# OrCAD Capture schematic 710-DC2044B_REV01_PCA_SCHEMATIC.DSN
size C; title: HIGH VOLTAGE BUCK/BOOST MULTI-CHEMISTRY BATTERY CHARGER; rev: 01
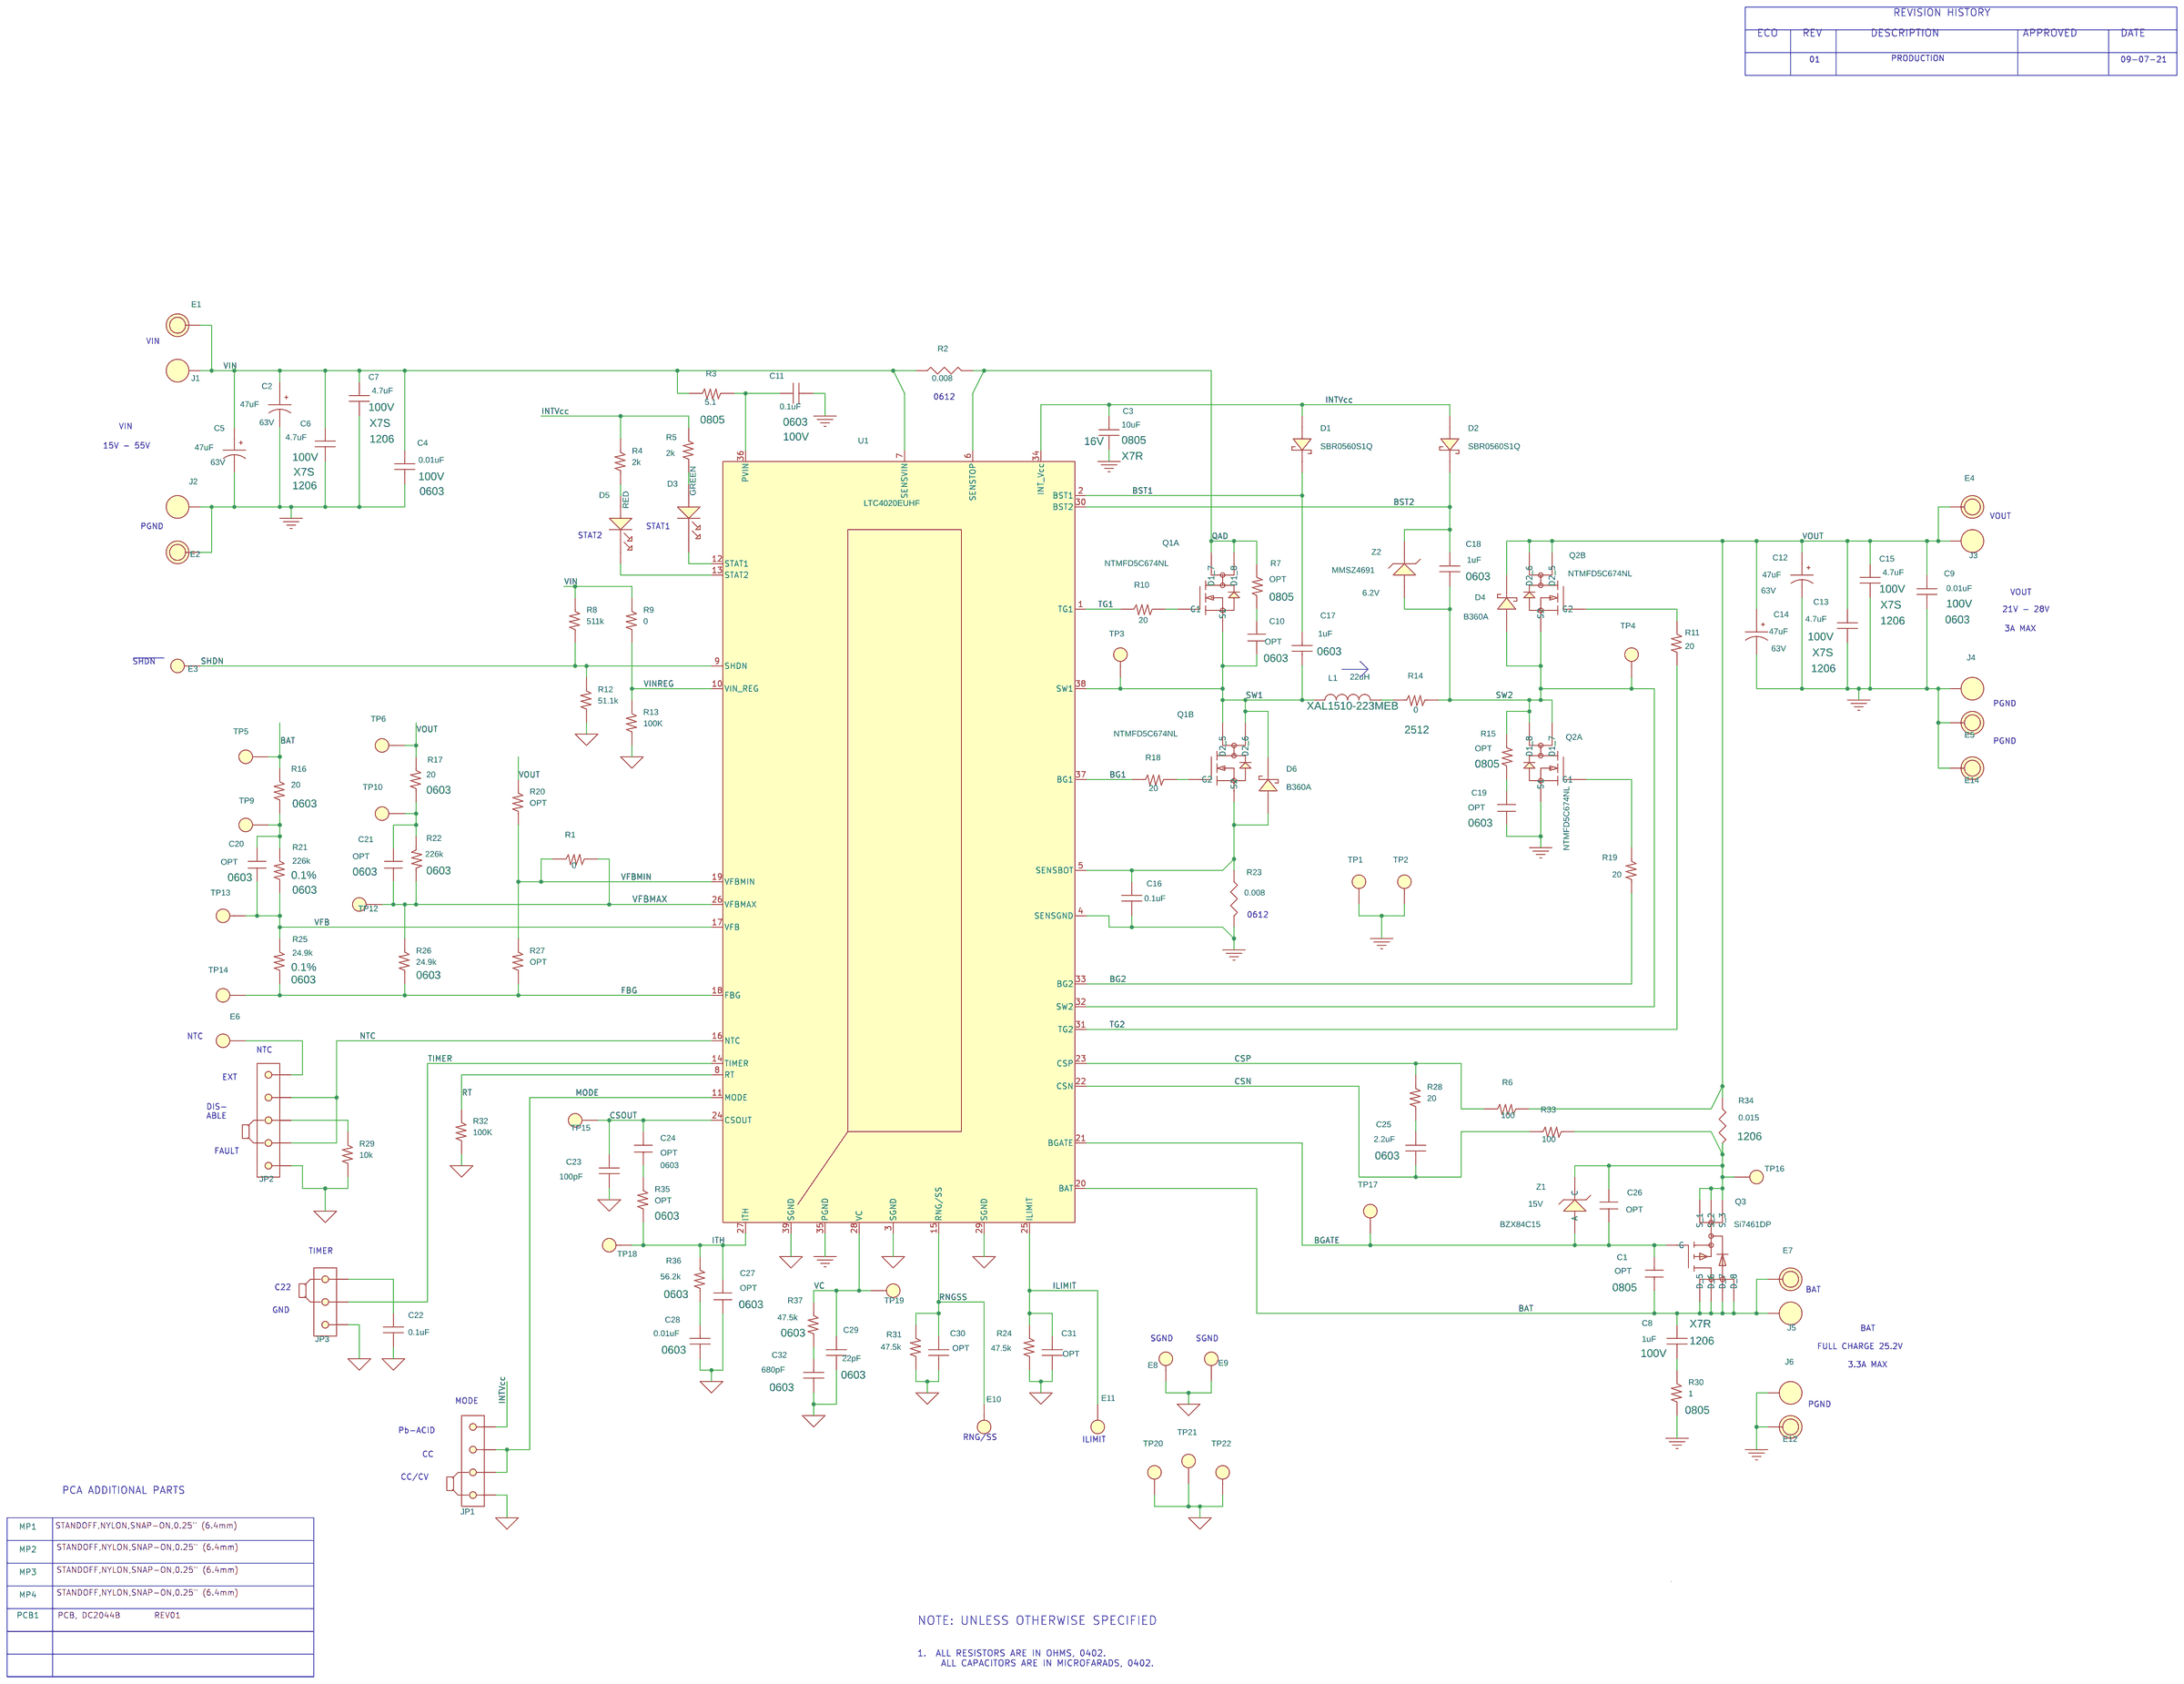
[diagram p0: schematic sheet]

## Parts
C1  OPT  [CC0805N]
C2  47uF  [PANASONIC_ZA_8X10.2]
C3  10uF  [CC0805N]
C4  0.01uF  [CC0603N]
C5  47uF  [PANASONIC_ZA_8X10.2]
C6  4.7uF  [CC1206N]
C7  4.7uF  [CC1206N]
C8  1uF  [CC1206N]
C9  0.01uF  [CC0603N]
C10  OPT  [CC0603N]
C11  0.1uF  [CC0603N]
C12  47uF  [PANASONIC_ZA_8X10.2]
C13  4.7uF  [CC1206N]
C14  47uF  [PANASONIC_ZA_8X10.2]
C15  4.7uF  [CC1206N]
C16  0.1uF  [CC0402N]
C17  1uF  [CC0603N]
C18  1uF  [CC0603N]
C19  OPT  [CC0603N]
C20  OPT  [CC0603N]
C21  OPT  [CC0603N]
C22  0.1uF  [CC0402N]
C23  100pF  [CC0402N]
C24  OPT  [CC0603N]
C25  2.2uF  [CC0603N]
C26  OPT  [CC0603N]
C27  OPT  [CC0603N]
C28  0.01uF  [CC0603N]
C29  22pF  [CC0603N]
C30  OPT  [CC0402N]
C31  OPT  [CC0402N]
C32  680pF  [CC0603N]
D1  SBR0560S1Q  [SOD-123N]
D2  SBR0560S1Q  [SOD-123N]
D3  GREEN  [LED_0603]
D4  B360A  [SMA-N]
D5  RED  [LED_0603]
D6  B360A  [SMA-N]
E1  TEST POINT  [MILLMAX2501]
E2  TEST POINT  [MILLMAX2501]
E3  TEST POINT  [MILLMAX2308]
E4  TEST POINT  [MILLMAX2501]
E5  TEST POINT  [MILLMAX2501]
E6  TEST POINT  [MILLMAX2308]
E7  TEST POINT  [MILLMAX2501]
E8  TEST POINT  [MILLMAX2308]
E9  TEST POINT  [MILLMAX2308]
E10  TEST POINT  [MILLMAX2308]
E11  TEST POINT  [MILLMAX2308]
E12  TEST POINT  [MILLMAX2501]
E14  TEST POINT  [MILLMAX2501]
J1  BANANA JACK  [KEY-575-4]
J2  BANANA JACK  [KEY-575-4]
J3  BANANA JACK  [KEY-575-4]
J4  BANANA JACK  [KEY-575-4]
J5  BANANA JACK  [KEY-575-4]
J6  BANANA JACK  [KEY-575-4]
JP1  HDR  [HD1X4-079]
JP2  HEADER  [HD1X5-079]
JP3  HDR  [HD1X3-079]
L1  22uH  [COILCRAFT-XAL1510]
MP1  STANDOFF  [MTG-8831]
MP2  STANDOFF  [MTG-8831]
MP3  STANDOFF  [MTG-8831]
MP4  STANDOFF  [MTG-8831]
PCB1  PCB, DC2044B
Q1  NTMFD5C674NL  [ONSEMI-DFN8-SO-8FL]  (sections A,B)
Q2  NTMFD5C674NL  [ONSEMI-DFN8-SO-8FL]  (sections A,B)
Q3  Si7461DP  [VISHAY_PPAK_SO-8]
R1  0  [CR0402N]
R2  0.008  [SUSUMU-PRL1632]
R3  5.1  [CR0805N]
R4  2k  [CR0402N]
R5  2k  [CR0402N]
R6  100  [CR0402N]
R7  OPT  [CR0805M]
R8  511k  [CR0402N]
R9  0  [CR0402N]
R10  20  [CR0402N]
R11  20  [CR0402N]
R12  51.1k  [CR0402N]
R13  100K  [CR0402N]
R14  0  [VISHAY-WSL_9-2512]
R15  OPT  [CR0805M]
R16  20  [CR0603N]
R17  20  [CR0603N]
R18  20  [CR0402N]
R19  20  [CR0402N]
R20  OPT  [CR0402N]
R21  226k  [CR0603N]
R22  226k  [CR0603N]
R23  0.008  [SUSUMU-PRL1632]
R24  47.5k  [CR0402N]
R25  24.9k  [CR0603N]
R26  24.9k  [CR0603N]
R27  OPT  [CR0402N]
R28  20  [CR0402N]
R29  10k  [CR0402N]
R30  1  [CR0805M]
R31  47.5k  [CR0402N]
R32  100K  [CR0402N]
R33  100  [CR0402N]
R34  0.015  [SUSUMU-KRL1632]
R35  OPT  [CR0603N]
R36  56.2k  [CR0603N]
R37  47.5k  [CR0603N]
TP1  TEST PAD  [PADSTYLE1]
TP2  TEST PAD  [PADSTYLE1]
TP3  TEST PAD  [PADSTYLE1]
TP4  TEST PAD  [PADSTYLE1]
TP5  TEST PAD  [PADSTYLE1]
TP6  TEST PAD  [PADSTYLE1]
TP9  TEST PAD  [PADSTYLE1]
TP10  TEST PAD  [PADSTYLE1]
TP12  TEST PAD  [PADSTYLE1]
TP13  TEST PAD  [PADSTYLE1]
TP14  TEST PAD  [PADSTYLE1]
TP15  TEST PAD  [PADSTYLE1]
TP16  TEST PAD  [PADSTYLE1]
TP17  TEST PAD  [PADSTYLE1]
TP18  TEST PAD  [PADSTYLE1]
TP19  TEST PAD  [PADSTYLE1]
TP20  TEST PAD  [PADSTYLE1]
TP21  TEST PAD  [PADSTYLE1]
TP22  TEST PAD  [PADSTYLE1]
U1  LTC4020EUHF  [LTC-UHF-38-1701]
XJP1  SHUNT  [SAMTEC-SHUNT-079]
XJP2  SHUNT  [SAMTEC-SHUNT-079]
XJP3  SHUNT  [SAMTEC-SHUNT-079]
Z1  BZX84C15  [SOT23-3N]
Z2  MMSZ4691  [SOD-123N]

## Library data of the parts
C1 = CAP_ALT: CAP., OPTION, 0805; CLASS: DISCRETE; PART_NUMBER: 150-3036; Package Size: 0805; Package Type: SMD
C2 C5 C12 C14 = CAP_P_ALT: CAP.,47uF,ALUM ELECT.,63V,20%,SMD,8.0x10.2 mm,AEC-Q200; CLASS: DISCRETE; Dielectric Type: ALUM ELECT.; Inventory Qty: 0; Manufacturer: PANASONIC; Manufacturer PN: EEHZA1J470P; PART_NUMBER: 150-0969; Package Size: SMD,8.0x10.2 mm; Rated Voltage: 63V; Tolerance: 20%
C3 = CAP: CAP.,10uF,X7R,16V,10%,0805; CLASS: DISCRETE; Dielectric Type: X7R; FPLIST: CC0805N,CC0805L,CC0805M; Inventory Qty: 22441; Manufacturer: TAIYO YUDEN; Manufacturer PN: EMK212BB7106MG-T; PART_NUMBER: 150-3231; Package Size: 0805; Package Type: SMD; Rated Voltage: 16V; Tolerance: 10%
C4 C9 = CAP: CAP.,0.01uF,X7R,100V,10%,0603,AEC-Q200; CLASS: DISCRETE; Dielectric Type: X7R; FPLIST: CC0603N,CC0603L,CC0603M; Inventory Qty: 20068; Manufacturer: MURATA; Manufacturer PN: GCJ188R72A103KA01D; PART_NUMBER: 150-0511; Package Size: 0603; Rated Voltage: 100V; Tolerance: 10%
C6 C7 C13 C15 = CAP: CAP.,4.7uF,X7S,100V,20%,1206; CLASS: DISCRETE; Dielectric Type: X7S; FPLIST: CC1206N,CC1206L,CC1206M; Inventory Qty: 11240; Manufacturer: AVX; Manufacturer PN: 12061Z475MAT2A; PART_NUMBER: 150-2278; Package Size: 1206; Rated Voltage: 100V; Tolerance: 20%
C8 = CAP: CAP.,1uF,X7R,100V,10%,1206,AEC-Q200; CLASS: DISCRETE; Dielectric Type: X7R; FPLIST: CC1206N,CC1206L,CC1206M; Inventory Qty: 800; Manufacturer: TDK; Manufacturer PN: CGA5L2X7R2A105K160AA; PART_NUMBER: 150-1253; Package Size: 1206; Rated Voltage: 100V; Temperature Coefficient: X7R; Tolerance: 10%
C10 C19-C21 C24 C26 C27 = CAP_ALT: CAP., OPTION, 0603; CLASS: DISCRETE; PART_NUMBER: 150-3038; Package Size: 0603; Package Type: SMD
C11 = CAP: CAP.,0.1uF,X7R,100V,10%,0603,AEC-Q200; CLASS: DISCRETE; Dielectric Type: X7R; FPLIST: CC0603N,CC0603L,CC0603M; Inventory Qty: 7960; Manufacturer: TAIYO YUDEN; Manufacturer PN: HMK107B7104KAHT; PART_NUMBER: 150-2623; Package Size: 0603; Rated Voltage: 100V; Tolerance: 10%
C16 C22 = CAP: CAP.,0.1uF,X7R,16V,10%,0402,AEC-Q200; CLASS: DISCRETE; Dielectric Type: X7R; FPLIST: CC0402N,CC0402L,CC0402M; Inventory Qty: 23025; Manufacturer: MURATA; Manufacturer PN: GCM155R71C104KA55D; PART_NUMBER: 150-0506; Package Size: 0402; Rated Voltage: 16V; Tolerance: 10%
C17 C18 = CAP: CAP.,1uF,X7R,16V,10%,0603; CLASS: DISCRETE; Dielectric Type: X7R; FPLIST: CC0603N,CC0603L,CC0603M; Inventory Qty: 29099; Manufacturer: KEMET; Manufacturer PN: C0603C105K4RAC7867; PART_NUMBER: 150-0179; Package Size: 0603; Rated Voltage: 16V; Tolerance: 10%
C23 = CAP: CAP.,100pF,C0G,50V,5%,0402; CLASS: DISCRETE; Dielectric Type: C0G; FPLIST: CC0402N,CC0402L,CC0402M; Inventory Qty: 62393; Manufacturer: AVX; Manufacturer PN: 04025A101JAT2A; PART_NUMBER: 150-0115; Package Size: 0402; Rated Voltage: 50V; Tolerance: 5%
C25 = CAP: CAP.,2.2uF,X7R,10V,10%,0603; CLASS: DISCRETE; Dielectric Type: X7R; FPLIST: CC0603N,CC0603L,CC0603M; Inventory Qty: 13521; Manufacturer: MURATA; Manufacturer PN: GRM188R71A225KE15D; PART_NUMBER: 150-2083; Package Size: 0603; Rated Voltage: 10V; Tolerance: 10%
C28 = CAP: CAP.,0.01uF,X7R,50V,10%,0603; CLASS: DISCRETE; Dielectric Type: X7R; FPLIST: CC0603N,CC0603L,CC0603M; Inventory Qty: 28283; Manufacturer: AVX; Manufacturer PN: 06035C103KAT2A; PART_NUMBER: 150-0002; Package Size: 0603; Rated Voltage: 50V; Tolerance: 10%
C29 = CAP: CAP.,22pF,C0G,25V,10%,0603; CLASS: DISCRETE; Dielectric Type: C0G; FPLIST: CC0603N,CC0603L,CC0603M; Inventory Qty: 12404; Manufacturer: AVX; Manufacturer PN: 06033A220KAT2A; PART_NUMBER: 150-3274; Package Size: 0603; Rated Voltage: 25V; Tolerance: 10%
C30 C31 = CAP: CAP., OPTION, 0402; CLASS: DISCRETE; FPLIST: CC0402N,CC0402L,CC0402M; PART_NUMBER: 150-3148; Package Size: 0402; Package Type: SMD
C32 = CAP: CAP.,680pF,C0G,25V,5%,0603; CLASS: DISCRETE; Dielectric Type: C0G; FPLIST: CC0603N,CC0603L,CC0603M; Inventory Qty: 8685; Manufacturer: AVX; Manufacturer PN: 06033A681JAT2A; PART_NUMBER: 150-0275; Package Size: 0603; Rated Voltage: 25V; Tolerance: 5%
D1 D2 = DIODE_SCHOTTKY_A_ALT: DIODE,SBR,60V,500mA,SOD123; CLASS: DISCRETE; Inventory Qty: 0; Manufacturer: DIODES INC.; Manufacturer PN: SBR0560S1Q-7; PART_NUMBER: 210-0561; Package Size: SOD-123; Package Type: SOD123; Rated Voltage or Zener Voltage: 60V
D3 = LED_ALT: LED,GREEN,WATER-CLEAR,0603; CLASS: DISCRETE; Inventory Qty: 49236; Manufacturer: LITE-ON; Manufacturer PN: LTST-C190KGKT; PART_NUMBER: 270-0051; Package Type: 0603
D4 D6 = DIODE_SCHOTTKY_A_ALT: DIODE,SCHOTTKY RECTIFIER,60V,3A,4.6mm X 2.92mm; CLASS: DISCRETE; FPLIST: SMA-N,SMA-L,SMA-M,SMA; Inventory Qty: 1450; Manufacturer: DIODES INC.; Manufacturer PN: B360A-13-F; Max Forward Current or Rated Power: 3A; PART_NUMBER: 210-0103; Package Type: 4.6mm X 2.92mm; Rated Voltage or Zener Voltage: 60V
D5 = LED_ALT: LED,RED,WATER-CLEAR,0603; CLASS: DISCRETE; Inventory Qty: 15266; Manufacturer: LITE-ON; Manufacturer PN: LTST-C193KRKT-5A; PART_NUMBER: 270-0070; Package Size: 0603 (1608 Metric); Package Type: 0603
E1 E2 E4 E5 E7 E12 E14 = TURRET_A: TEST POINT,TURRET,0.094" MTG. HOLE,PCB 0.062" THK; CLASS: IO; Inventory Qty: 823526; Manufacturer: MILL-MAX; Manufacturer PN: 2501-2-00-80-00-00-07-0; PART_NUMBER: 260-0003
E3 E6 E8-E11 = TEST_POINT_.156_MILL-MAX_2308: TEST POINT,TURRET,0.064" MTG. HOLE,PCB 0.062" THK; CLASS: IO; FPLIST: MILLMAX2308,MILLMAX2308-2; Inventory Qty: 1142083; Manufacturer: MILL-MAX; Manufacturer PN: 2308-2-00-80-00-00-07-0; PART_NUMBER: 260-0004
J1-J6 = BANANA_KEYSTONE-575-4_C: CONN.,BANANA JACK,FEMALE,THT,NON-INSULATED,SWAGE,0.218"; CLASS: IO; Inventory Qty: 203061; Manufacturer: KEYSTONE; Manufacturer PN: 575-4; PART_NUMBER: 250-0428
JP1 = HDR1X4: CONN.,HDR,MALE,1x4,2mm,VERT,ST,THT; CLASS: IO; Inventory Qty: 11710; Manufacturer: SULLINS CONNECTOR SOLUTIONS; Manufacturer PN: NRPN041PAEN-RC; PART_NUMBER: 250-0431
JP2 = HDR1X5: CONN.,HEADER,MALE,1X5,2mm,ST, THT; CLASS: IO; Inventory Qty: 950; Manufacturer: SULLINS CONNECTOR SOLUTIONS; Manufacturer PN: NRPN051PAEN-RC; PART_NUMBER: 250-0564
JP3 = 1X3: CONN.,HDR,MALE,1x3,2mm,VERT,ST,THT,NO SUBS. ALLOWED; CLASS: IO; Inventory Qty: 7904; Manufacturer: SAMTEC; Manufacturer PN: TMM-103-02-L-S; PART_NUMBER: 250-0638
L1 = IND_ALT: IND.,22uH,PWR,20%,14A,16mOHMS,16.2x15.2mm,AEC-Q200; CLASS: DISCRETE; Inventory Qty: 0; Manufacturer: COILCRAFT; Manufacturer PN: XAL1510-223MEB; PART_NUMBER: 200-0363; Package Size: 16.2x15.2mm; Tolerance: 20%
MP1-MP4 = BLANK_MECHANICAL_PART: STANDOFF,NYLON,SNAP-ON,0.25" (6.4mm); CLASS: DISCRETE; Inventory Qty: 227624; Manufacturer: KEYSTONE; Manufacturer PN: 8831; PART_NUMBER: 763-0006
PCB1 = BLANK_PCB_PART: BOM Notes: REV01; CLASS: DISCRETE; Inventory Qty: 0; Manufacturer: ADI APPROVED SUPPLIER; Manufacturer PN: 600-DC2044B; PART_NUMBER: 600-DC2044B
Q1 Q2 = DUAL_8P_N-CH_TYPE1A: XSTR.,MOSFET,DUAL N-CH,60V,42A,DFN-8 (SO8FL); CLASS: DISCRETE; Inventory Qty: 0; Manufacturer: ON Semiconductor; Manufacturer PN: NTMFD5C674NLT1G; PART_NUMBER: 240-0596; Package Size: DFN-8; Package Type: DFN-8 (SO8FL); Polarity: N-Channel; Rated Voltage: 60V
Q3 = 8P_P-CH_TYPE1A: XSTR.,MOSFET, P-CH,60V,8.6A,PowerPAK SO-8; CLASS: DISCRETE; Inventory Qty: 1926; Manufacturer: VISHAY; Manufacturer PN: Si7461DP-T1-GE3; PART_NUMBER: 240-0180; Package Type: PowerPAK SO-8; Rated Voltage: 60V
R1 R9 = RES_ALT: RES.,0 OHM,1/16W,0402; CLASS: DISCRETE; FPLIST: CR0402N,CR0402L,CR0402M; Inventory Qty: 264417; Manufacturer: ROHM; Manufacturer PN: MCR01MZPJ000; PART_NUMBER: 100-0215; Package Size: 0402; Rated Power: 1/16W
R2 R23 = RES: RES.,0.008 OHMS,1%,1W,1206,LONG-SIDE,SENSE; CLASS: DISCRETE; Inventory Qty: 0; Manufacturer: Susumu; Manufacturer PN: PRL1632-R008-F-T1; PART_NUMBER: 100-1805; Package Size: 1206,LONG-SIDE; Rated Power: 1W; Temperature Coefficient: 0/ +350ppm; Tolerance: 1%
R3 = RES_ALT: RES.,5.1 OHMS,5%,1/8W,0805,AEC-Q200; CLASS: DISCRETE; FPLIST: CR0805N,CR0805L,CR0805M; Inventory Qty: 9698; Manufacturer: VISHAY; Manufacturer PN: CRCW08055R10JNEA; PART_NUMBER: 100-2080; Package Size: 0805; Rated Power: 1/8W; Temperature Coefficient: +/-200PPM; Tolerance: 5%
R4 R5 = RES_ALT: RES.,2k OHMS,1%,1/16W,0402,AEC-Q200; CLASS: DISCRETE; FPLIST: CR0402N,CR0402L,CR0402M; Inventory Qty: 54049; Manufacturer: VISHAY; Manufacturer PN: CRCW04022K00FKED; PART_NUMBER: 100-0018; Package Size: 0402; Rated Power: 1/16W; Temperature Coefficient: 100ppm/C; Tolerance: 1%
R6 R33 = RES_ALT: RES.,100 OHMS,1%,1/16W,0402,AEC-Q200; CLASS: DISCRETE; FPLIST: CR0402N,CR0402L,CR0402M; Inventory Qty: 89473; Manufacturer: KOA SPEER; Manufacturer PN: RK73H1ETTP1000F; PART_NUMBER: 100-0175; Package Size: 0402; Rated Power: 1/16W; Temperature Coefficient: 100ppm/C; Tolerance: 1%
R7 R15 = RES_ALT: RES., OPTION, 0805; CLASS: DISCRETE; PART_NUMBER: 100-2558; Package Size: 0805
R8 = RES_ALT: RES.,511k OHMS,1%,1/16W,0402,AEC-Q200; CLASS: DISCRETE; FPLIST: CR0402N,CR0402L,CR0402M; Inventory Qty: 20064; Manufacturer: NIC; Manufacturer PN: NRC04F5113TRF; PART_NUMBER: 100-0583; Package Size: 0402; Rated Power: 1/16W; Temperature Coefficient: +/-100PPM; Tolerance: 1%
R10 R11 R18 R19 = RES_ALT: RES.,20 OHMS,1%,1/16W,0402; CLASS: DISCRETE; FPLIST: CR0402N,CR0402L,CR0402M; Inventory Qty: 8000; Manufacturer: VISHAY; Manufacturer PN: CRCW040220R0FKED; PART_NUMBER: 100-2322; Package Size: 0402; Rated Power: 1/16W; Temperature Coefficient: 100ppm/C; Tolerance: 1%
R12 = RES_ALT: RES.,51.1k OHMS,1%,1/16W,0402,AEC-Q200; CLASS: DISCRETE; FPLIST: CR0402N,CR0402L,CR0402M; Inventory Qty: 20000; Manufacturer: STACKPOLE ELECTRONICS, INC.; Manufacturer PN: RMCF0402FT51K1; PART_NUMBER: 100-2544; Package Size: 0402; Rated Power: 1/16W; Temperature Coefficient: 100ppm/C; Tolerance: 1%
R13 R32 = RES_ALT: RES.,100k OHMS,1%,1/16W,0402,AEC-Q200; CLASS: DISCRETE; FPLIST: CR0402N,CR0402L,CR0402M; Inventory Qty: 92256; Manufacturer: NIC; Manufacturer PN: NRC04F1003TRF; PART_NUMBER: 100-0601; Package Size: 0402; Rated Power: 1/16W; Temperature Coefficient: 100PPM; Tolerance: 1%
R14 = RES_ALT: RES.,0 OHM,200A,2512,COPPER,SENSE; CLASS: DISCRETE; FPLIST: CR2512N,CR2512L,CR2512M,VISHAY-WSL2512; Inventory Qty: 7479; Manufacturer: VISHAY; Manufacturer PN: WSL251200000ZEA9; PART_NUMBER: 100-0588; Package Size: 2512; Rated Power: 200A; Temperature Coefficient: +/-3900ppm
R16 R17 = RES_ALT: RES.,20 OHMS,1%,1/10W,0603; CLASS: DISCRETE; FPLIST: CR0603N,CR0603L,CR0603M; Inventory Qty: 10000; Manufacturer: YAGEO; Manufacturer PN: RC0603FR-0720RL; PART_NUMBER: 100-0703; Package Size: 0603; Rated Power: 1/10W; Temperature Coefficient: 100PPM; Tolerance: 1%
R20 R27 = RES_ALT: RES., OPTION, 0402; CLASS: DISCRETE; PART_NUMBER: 100-0357; Package Size: 0402
R21 = RES_ALT: RES.,226k OHMS,0.1%,1/10W,0603,High Stability; CLASS: DISCRETE; Inventory Qty: 4724; Manufacturer: VISHAY; Manufacturer PN: TNPW0603226KBEEA; PART_NUMBER: 100-2083; Package Size: 0603; Rated Power: 1/10W; Temperature Coefficient: +/-25PPM; Tolerance: 0.1%
R22 = RES_ALT: RES.,226k OHMS,1%,1/10W,0603; CLASS: DISCRETE; FPLIST: CR0603N,CR0603L,CR0603M; Inventory Qty: 26500; Manufacturer: NIC; Manufacturer PN: NRC06F2263TRF; PART_NUMBER: 100-2671; Package Size: 0603; Rated Power: 1/10W; Temperature Coefficient: 100ppm/C; Tolerance: 1%
R24 R31 = RES_ALT: RES.,47.5k OHMS,1%,1/16W,0402; CLASS: DISCRETE; FPLIST: CR0402N,CR0402L,CR0402M; Inventory Qty: 10000; Manufacturer: NIC; Manufacturer PN: NRC04F4752TRF; PART_NUMBER: 100-0390; Package Size: 0402; Rated Power: 1/16W; Temperature Coefficient: 100ppm/C; Tolerance: 1%
R25 = RES_ALT: RES.,24.9k OHMS,0.1%,1/8W,0603,AEC-Q00; CLASS: DISCRETE; Inventory Qty: 0; Manufacturer: VISHAY; Manufacturer PN: TNPW060324K9BEEA; PART_NUMBER: 100-1806; Package Size: 0603; Rated Power: 1/8W; Temperature Coefficient: +/-25ppm; Tolerance: 0.1%
R26 = RES_ALT: RES.,24.9k OHMS,1%,1/10W,0603,AEC-Q200; CLASS: DISCRETE; FPLIST: CR0603N,CR0603L,CR0603M; Inventory Qty: 22314; Manufacturer: NIC; Manufacturer PN: NRC06F2492TRF; PART_NUMBER: 100-0037; Package Size: 0603; Rated Power: 1/10W; Temperature Coefficient: 100ppm/C; Tolerance: 1%
R28 = RES_ALT: RES.,20 OHMS,1%,1/16W,0402,AEC-Q200; CLASS: DISCRETE; FPLIST: CR0402N,CR0402L,CR0402M; Inventory Qty: 29845; Manufacturer: NIC; Manufacturer PN: NRC04F20R0TRF; PART_NUMBER: 100-0250; Package Size: 0402; Rated Power: 1/16W; Temperature Coefficient: 100ppm; Tolerance: 1%
R29 = RES_ALT: RES.,10k OHMS,1%,1/10W,0402,AEC-Q200; CLASS: DISCRETE; FPLIST: CR0402N,CR0402L,CR0402M; Inventory Qty: 88953; Manufacturer: KOA SPEER; Manufacturer PN: RK73H1ETTP1002F; PART_NUMBER: 100-0724; Package Size: 0402; Rated Power: 1/10W; Temperature Coefficient: 100ppm; Tolerance: 1%
R30 = RES_ALT: RES.,1 OHM,1%,1/8W,0805,AEC-Q200; CLASS: DISCRETE; FPLIST: CR0805N,CR0805L,CR0805M; Inventory Qty: 5000; Manufacturer: VISHAY; Manufacturer PN: CRCW08051R00FKEA; PART_NUMBER: 100-0932; Package Size: 0805; Rated Power: 1/8W; Temperature Coefficient: +/-100PPM; Tolerance: 1%
R34 = RES: RES.,0.015 OHMS,1%,3/4W,1206,AEC-Q200,METAL,SENSE; CLASS: DISCRETE; Inventory Qty: 0; Manufacturer: SUSUMU; Manufacturer PN: KRL1632E-C-R015-F-T1; PART_NUMBER: 100-1807; Package Size: 1206; Rated Power: 3/4W; Temperature Coefficient: +/-50ppm; Tolerance: 1%
R35 = RES_ALT: RES., OPTION, 0603; CLASS: DISCRETE; PART_NUMBER: 100-2374; Package Size: 0603
R36 = RES_ALT: RES.,56.2k OHMS,1%,1/10W,0603,AEC-Q200; CLASS: DISCRETE; FPLIST: CR0603N,CR0603L,CR0603M; Inventory Qty: 50019; Manufacturer: NIC; Manufacturer PN: NRC06F5622TRF; PART_NUMBER: 100-2697; Package Size: 0603; Rated Power: 1/10W; Temperature Coefficient: 100ppm/C; Tolerance: 1%
R37 = RES_ALT: RES.,47.5k OHMS,1%,1/10W,0603; CLASS: DISCRETE; FPLIST: CR0603N,CR0603L,CR0603M; Inventory Qty: 67863; Manufacturer: VISHAY; Manufacturer PN: CRCW060347K5FKEA; PART_NUMBER: 100-2554; Package Size: 0603; Rated Power: 1/10W; Temperature Coefficient: 100ppm/C; Tolerance: 1%
TP1-TP6 TP9 TP10 TP12-TP22 = PAD_STYLE_C: TESTPOINT, PCB COPPER FEATURE; CLASS: IO; PART_NUMBER: PCBPADS-8
U1 = LTC4020EUHF: IC,55V BUCK-BOOST BATTERY CHARGER,38-pin QFN; CLASS: IC; Inventory Qty: 0; Manufacturer: LINEAR TECH.; Manufacturer PN: LTC4020EUHF#PBF; PART_NUMBER: LTC4020EUHF#PBF; Package Size: QFN-38; Package Type: 38-pin QFN
XJP1-XJP3 = SHUNT_2MM: CONN.,SHUNT,FEMALE,2-POS,2mm; CLASS: MECHANICAL; Inventory Qty: 268916; Manufacturer: SAMTEC; Manufacturer PN: 2SN-BK-G; PART_NUMBER: 250-0419
Z1 = ZENER_SOT: DIODE,ZENER,15V,350mW,SOT-23,AEC-Q101; CLASS: DISCRETE; FPLIST: SOT23-3N,SOT23-3L,SOT23-3M; Inventory Qty: 0; Manufacturer: NEXPERIA; Manufacturer PN: BZX84-C15,215; Max Forward Current or Rated Power: 350mW; PART_NUMBER: 210-0510; Package Type: SOT-23; Rated Voltage or Zener Voltage: 15V
Z2 = ZENER_ALT: DIODE,ZENER,6.2V,500mW,SOD-123,AEC-Q101; CLASS: DISCRETE; Inventory Qty: 0; Manufacturer: VISHAY; Manufacturer PN: MMSZ4691-E3-08; PART_NUMBER: 210-0562; Package Size: SOD-123; Package Type: SOD-123; Rated Voltage or Zener Voltage: 6.2V

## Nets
GND_POWER: C2.2 C3.2 C4.2 C5.2 C6.2 C7.2 C9.2 C11.2 C12.2 C13.2 C14.2 C15.2 C16.2 C19.1 E2.1 E5.1 E12.1 E14.1 J2.1 J4.1 J6.1 Q2.1(S1) R23.2 R30.2 TP1.1 TP2.1 U1.4(SENSGND) U1.35(PGND)
GND_SIGNAL: C22.2 C23.2 C27.2 C28.2 C29.2 C30.2 C31.2 C32.2 E8.1(A) E9.1(A) JP1.4 JP2.5 JP3.3 R12.2 R13.2 R24.2 R29.2 R31.2 R32.2 TP20.1 TP21.1 TP22.1 U1.3(SGND) U1.29(SGND) U1.39(SGND)
VIN: C2.1 C4.1 C5.1 C6.1 C7.1 E1.1 J1.1 R2.1 R3.1 R8.1 R9.1 U1.7(SENSVIN)
VINREG: R9.2 R13.1 U1.10(VIN_REG)
BAT: C1.2 C8.1 E7.1 J5.1 Q3.5(D) Q3.6(D) Q3.7(D) Q3.8(D) R16.1 TP5.1 U1.20(BAT)
BG1: R18.1 U1.37(BG1)
BG2: R19.2 U1.33(BG2)
BGATE: C1.1 C26.2 Q3.4(G) TP17.1 U1.21(BGATE) Z1.1(A)
BST1: C17.1 D1.1(C) U1.2(BST1)
BST2: C18.1 D2.1(C) U1.30(BST2) Z2.1(C)
CSN: C25.2 R33.1 U1.22(CSN)
CSOUT: C23.1 C24.1 TP15.1 U1.24(CSOUT)
CSP: R6.1 R28.1 U1.23(CSP)
FBG: R25.2 R26.2 R27.2 TP14.1 U1.18(FBG)
ILIMIT: C31.1 E11.1(A) R24.1 U1.25(ILIMIT)
INTVcc: C3.1 D1.2(A) D2.2(A) JP1.1 R4.1 R5.1 U1.34(INT_Vcc)
ITH: C27.1 R35.2 R36.1 TP18.1 U1.27(ITH)
MODE: JP1.2 JP1.3 U1.11(MODE)
NTC: JP2.2 JP2.4 U1.16(NTC)
QAD: Q1.7(D1) Q1.8(D1) R2.2 R7.2 U1.6(SENSTOP)
RNGSS: C30.1 E10.1(A) R31.1 U1.15(RNG/SS)
RT: R32.1 U1.8(RT)
SHDN: E3.1(A) R8.2 R12.1 U1.9(SHDN)
SW1: C10.1 C17.2 D6.1(C) L1.1 Q1.1(S1) Q1.5(D2) Q1.6(D2) TP3.1 U1.38(SW1)
SW2: C18.2 D4.2(A) Q2.3(S2) Q2.7(D1) Q2.8(D1) R14.2 R15.2 TP4.1 U1.32(SW2) Z2.2(A)
TG1: R10.1 U1.1(TG1)
TG2: R11.2 U1.31(TG2)
TIMER: JP3.2 U1.14(TIMER)
VC: C29.1 R37.1 TP19.1 U1.28(VC)
VFB: C20.2 R21.2 R25.1 TP13.1 U1.17(VFB)
VFBMAX: C21.2 R1.2 R22.2 R26.1 TP12.1 U1.26(VFBMAX)
VFBMIN: R1.1 R20.2 R27.1 U1.19(VFBMIN)
VOUT: C9.1 C12.1 C13.1 C14.1 C15.1 D4.1(C) E4.1 J3.1 Q2.5(D2) Q2.6(D2) R6.2 R17.1 R20.1 R34.1 TP6.1
N16559762: C20.1 R16.2 R21.1 TP9.1
N16563575: C32.1 R37.2
N16563579: C28.1 R36.2
N16567930: C24.2 R35.1
N16574178: C21.1 R17.2 R22.1 TP10.1
N16590650: C16.1 D6.2(A) Q1.3(S2) R23.1 U1.5(SENSBOT)
N16591324: C10.2 R7.1
N16591456: C19.2 R15.1
N16600107: D3.1(CATHODE) U1.12(STAT1)
N16600116: D5.1(CATHODE) U1.13(STAT2)
N16621792: C26.1 Q3.1(S) Q3.2(S) Q3.3(S) R33.2 R34.2 TP16.1 Z1.3(C)
N16768872: E6.1(A) JP2.1
N16771108: L1.2 R14.1
N16813716: C22.1 JP3.1
N16858640: C11.1 R3.2 U1.36(PVIN)
N16860808: D5.2(ANODE) R4.2
N16860845: D3.2(ANODE) R5.2
N16865080: JP2.3 R29.1
N16868558: C25.1 R28.2
N16872134: Q2.4(G2) R11.1
N16872774: Q2.2(G1) R19.1
N16881464: C8.2 R30.1
N16911653: Q1.4(G2) R18.2
N16911667: Q1.2(G1) R10.2

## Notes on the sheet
- REVISION HISTORY
- ECO
- REV
- DESCRIPTION
- APPROVED
- DATE
- 01
- PRODUCTION
- 09-07-21
- VIN
- 0612
- VIN
- 15V - 55V
- VOUT
- PGND
- STAT2
- STAT1
- VOUT
- 21V - 28V
- 3A MAX
- SHDN
- PGND
- PGND
- 0612
- NTC
- NTC
- EXT
- DIS-
  ABLE
- FAULT
- TIMER
- C22
- BAT
- GND
- BAT
- SGND
- SGND
- FULL CHARGE 25.2V
- 3.3A MAX
- MODE
- PGND
- Pb-ACID
- RNG/SS
- ILIMIT
- CC
- CC/CV
- PCA ADDITIONAL PARTS
- NOTE: UNLESS OTHERWISE SPECIFIED
- 1.  ALL RESISTORS ARE IN OHMS, 0402.
       ALL CAPACITORS ARE IN MICROFARADS, 0402.
